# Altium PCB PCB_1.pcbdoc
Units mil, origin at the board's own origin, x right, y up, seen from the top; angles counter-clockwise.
Board outline 2237.91 x 3835.19 mil, 2 copper layers (Top Layer, Bottom Layer); 69 components, 62 nets, 255 pads, 151 vias.
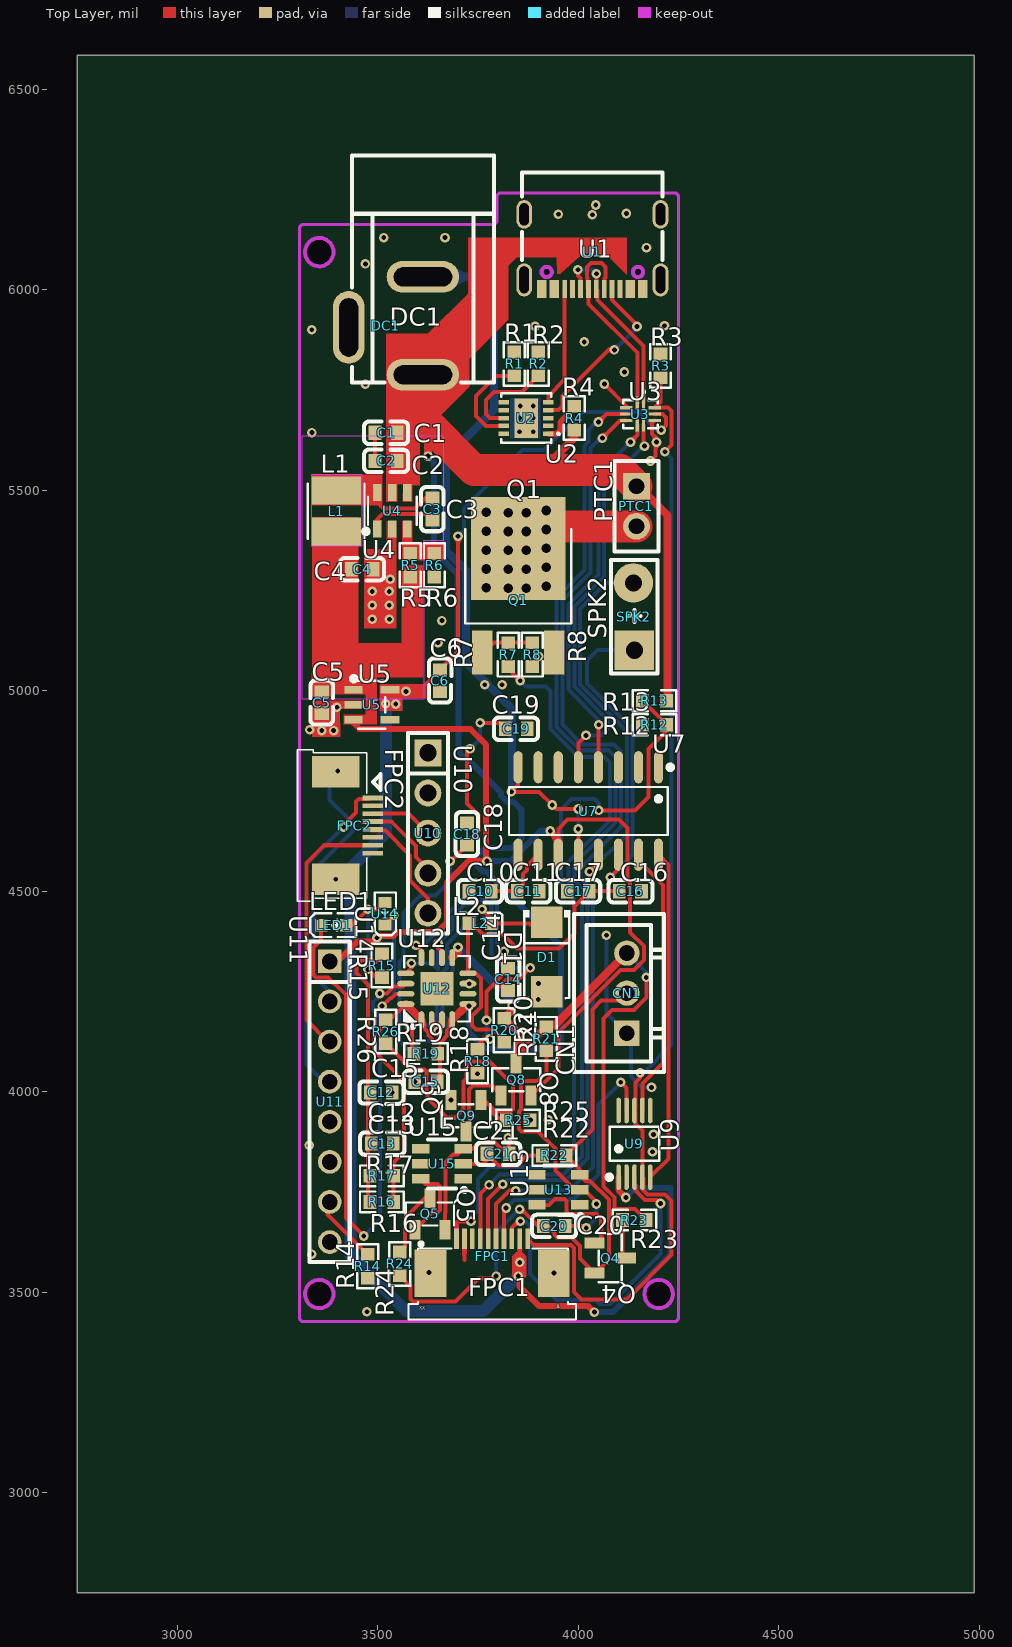
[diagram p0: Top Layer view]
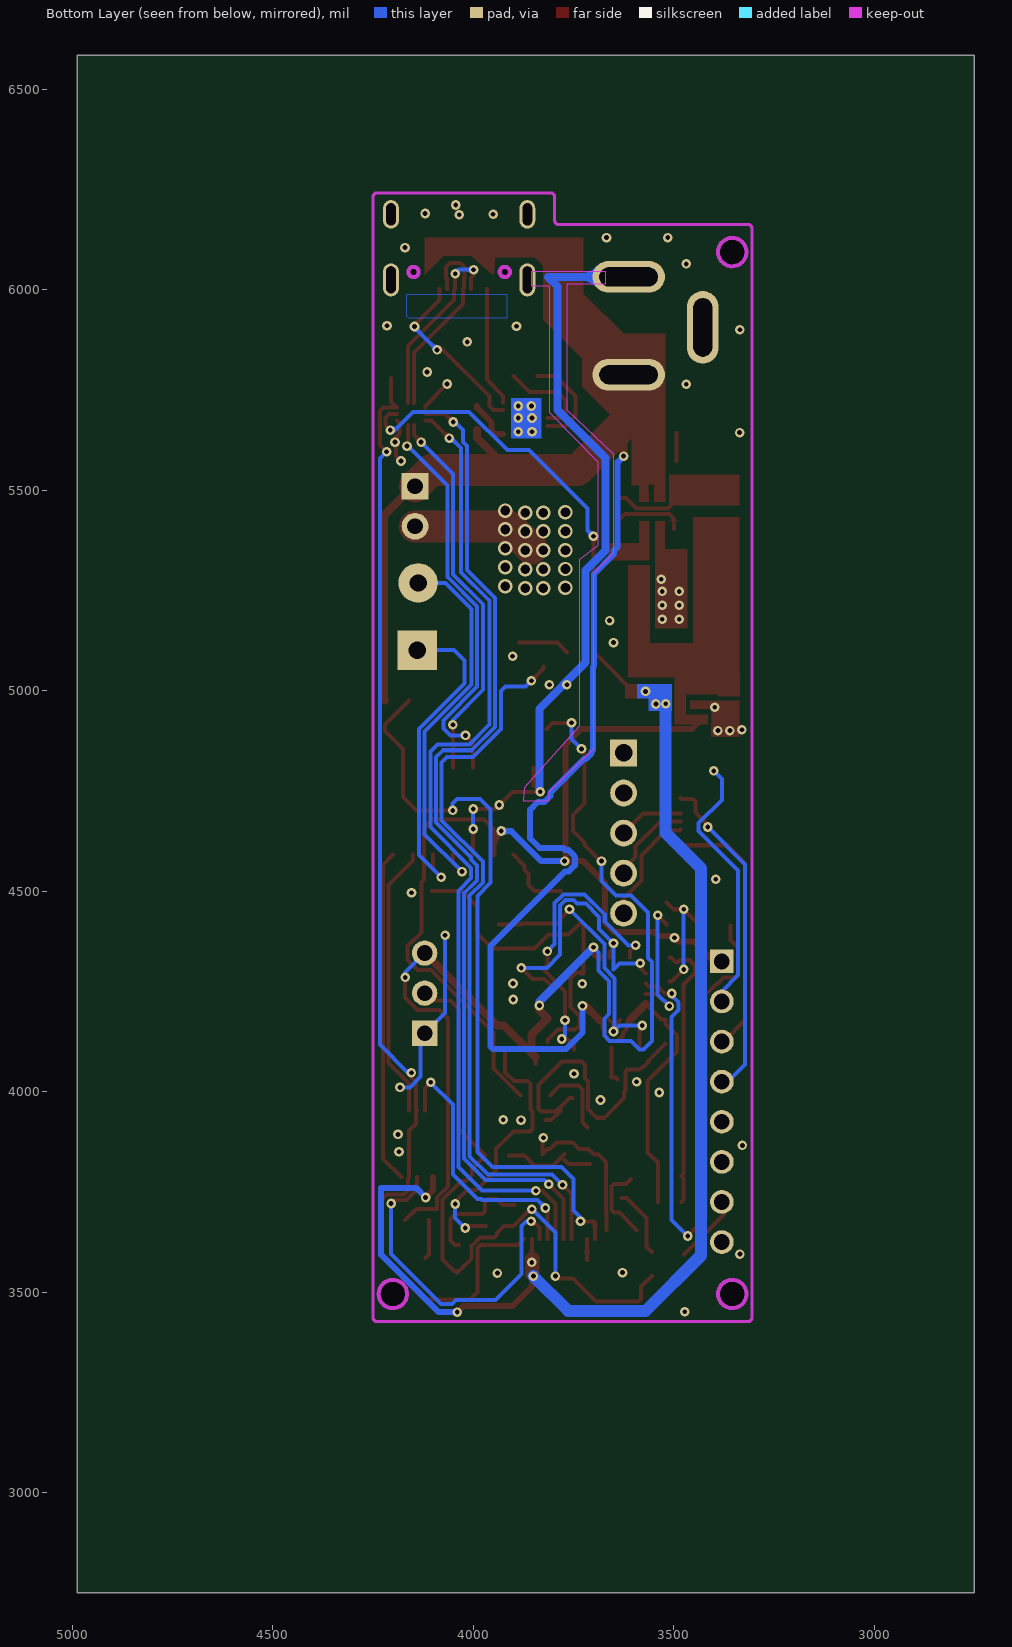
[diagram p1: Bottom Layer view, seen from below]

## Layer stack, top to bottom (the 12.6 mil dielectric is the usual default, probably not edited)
Top Layer: signal copper (thickness not stored)
Dielectric: dielectric 12.6, FR-4, Dk 4.8
Bottom Layer: signal copper (thickness not stored)

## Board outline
4987.91,2750 2750,2750 2750,6585.19 4987.91,6585.19
cut-out: 3389.43,6093.89 ccw(c3354,6093.67) 3318.57,6093.89 ccw(c3354,6094.11)
cut-out: 3389.43,3495.47 ccw(c3354,3495.25) 3318.57,3495.47 ccw(c3354,3495.69)
cut-out: 4235.89,3495.47 ccw(c4200.45,3495.47) 4165.02,3495.47 ccw(c4200.45,3495.47)

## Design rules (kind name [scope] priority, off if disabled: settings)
BoardOutlineClearance copperThickness1oz [All] p0: genericclearance=10 ignorepadtopadclearanceinfootprint=FALSE except(0: Arc-SplitContinuation Track-SplitContinuation SMDPad-SplitContinuation THPad-SplitContinuation Via-SplitContinuation Fill-SplitContinuation Poly-SplitContinuation Region-SplitContinuation Text-SplitContinuation; 6: Track-CutoutEdge SMDPad-CutoutEdge THPad-CutoutEdge Via-CutoutEdge Region-CutoutEdge; 11.8: Track-OutlineEdge SMDPad-OutlineEdge THPad-OutlineEdge Via-OutlineEdge Fill-OutlineEdge Region-OutlineEdge Poly-OutlineEdge Text-OutlineEdge Fill-CutoutEdge)
BoardOutlineClearance copperThickness2oz [All] p0: genericclearance=10 ignorepadtopadclearanceinfootprint=FALSE except(0: Arc-SplitContinuation Track-SplitContinuation SMDPad-SplitContinuation THPad-SplitContinuation Via-SplitContinuation Fill-SplitContinuation Poly-SplitContinuation Region-SplitContinuation Text-SplitContinuation; 6: Track-CutoutEdge SMDPad-CutoutEdge THPad-CutoutEdge Via-CutoutEdge Region-CutoutEdge; 11.8: Track-OutlineEdge SMDPad-OutlineEdge THPad-OutlineEdge Via-OutlineEdge Fill-OutlineEdge Region-OutlineEdge Poly-OutlineEdge Text-OutlineEdge Fill-CutoutEdge)
Clearance copperThickness1oz [(InNet('GND') OR InNet('3V3') OR InNet('ADC_VIN') OR InNet('$2N1457') OR InNet('$2N1458') OR InNet('VIN') OR InNet('5V') OR InNet('$2N1719') OR InNet('ESP_TX') OR InNet('ESP_RX') OR InNet('DN1') OR InNet('DP1') OR InNet('$2N173') OR InNet('$2N169') OR InNet('$2N860') OR InNet('$2N846') OR InNet('$2N1461') OR InNet('$2N861') OR InNet('DAC') OR InNet('SPK2') OR InNet('SPK1') OR InNet('SCK') OR InNet('DOUT') OR InNet('CC1') OR InNet('DN') OR InNet('DP') OR InNet('CC2') OR InNet('USBDM') OR InNet('USBDP') OR InNet('CH7800_RX') OR InNet('CH7800_TX') OR InNet('SW') OR InNet('PTC') OR InNet('$2N3080') OR InNet('GPIO17') OR InNet('GPIO16') OR InNet('GPIO15') OR InNet('SCL') OR InNet('SDA') OR InNet('AD0') OR InNet('XDA') OR InNet('XCL') OR InNet('INT') OR InNet('$2N24838') OR InNet('$2N25111') OR InNet('$2N25200') OR InNet('$2N25373') OR InNet('$2N25939') OR InNet('BAT+') OR InNet('$2N25975') OR InNet('$2N26224') OR InNet('$2N25852') OR InNet('$2N24540') OR InNet('$2N24753') OR InNet('$2N26433') OR InNet('$2N26509') OR InNet('$2N26582') OR InNet('$2N26578') OR InNet('$2N27775') OR InNet('$2N27867') OR InNet('$2N28041') OR InNet('$2N26613'))] p1: gap=7 ignorepadtopadclearanceinfootprint=FALSE except(4: Track-Track; 6: Track-SMDPad SMDPad-SMDPad Track-THPad SMDPad-THPad THPad-THPad Track-Via SMDPad-Via THPad-Via Via-Via SMDPad-Fill THPad-Fill Via-Fill Fill-Fill Track-Region SMDPad-Region THPad-Region Via-Region Region-Region Track-Poly SMDPad-Poly THPad-Poly Via-Poly Fill-Poly Region-Poly Poly-Poly Track-Text SMDPad-Text THPad-Text Via-Text Fill-Text Region-Text Poly-Text Text-Text; 6.9: Track-Hole SMDPad-Hole THPad-Hole Via-Hole Fill-Hole Region-Hole Poly-Hole Text-Hole Sheet-Hole; 11.8: Track-Fill Fill-Region Track-Sheet SMDPad-Sheet THPad-Sheet Via-Sheet Fill-Sheet Region-Sheet Poly-Sheet Text-Sheet)
Clearance copperThickness2oz [All] p1: gap=7 ignorepadtopadclearanceinfootprint=FALSE except(6: Track-SMDPad SMDPad-SMDPad Track-THPad SMDPad-THPad THPad-THPad Track-Via SMDPad-Via THPad-Via Via-Via SMDPad-Fill THPad-Fill Via-Fill Fill-Fill Track-Region SMDPad-Region THPad-Region Via-Region Region-Region Track-Poly SMDPad-Poly THPad-Poly Via-Poly Fill-Poly Region-Poly Poly-Poly Track-Text SMDPad-Text THPad-Text Via-Text Fill-Text Region-Text Poly-Text Text-Text; 6.9: Track-Hole SMDPad-Hole THPad-Hole Via-Hole Fill-Hole Region-Hole Poly-Hole Text-Hole Sheet-Hole; 8: Track-Track; 11.8: Track-Fill Fill-Region Track-Sheet SMDPad-Sheet THPad-Sheet Via-Sheet Fill-Sheet Region-Sheet Poly-Sheet Text-Sheet)
DiffPairsRouting differentialPair [All] p1: maxuncoupledlength=10 minlimit=6 maxlimit=6 mostfreqgap=6 toplayer_minwidth=5 toplayer_prefwidth=10 toplayer_maxwidth=100 bottomlayer_minwidth=5 bottomlayer_prefwidth=10 bottomlayer_maxwidth=100
PasteMaskExpansion pasteMaskExpansion [All] p1: expansion=0
PlaneConnect innerPlane [All] p1: planeconnectstyle=Relief reliefexpansion=20 reliefentries=4 reliefconductorwidth=10 reliefairgap=10
PolygonConnect copperRegion [All] p1: connectstyle=Relief reliefentries=4 reliefconductorwidth=10 polygonreliefangle="90 Angle" airgapwidth=10
RoutingVias viaSize [All] p1: viastyle="Through Hole" holewidth=12.0078 minholewidth=11.811 maxholewidth=248.0314 width=24.0158 minwidth=19.685 maxwidth=393.7008
SolderMaskExpansion solderMaskExpansion [All] p1: useseparateexpansions=TRUE expansion=2 expansionbottom=2
Width copperThickness1oz [All] p1: maxlimit=100 minlimit=5 preferedwidth=10
Width copperThickness2oz [All] p1: maxlimit=100 minlimit=8 preferedwidth=10

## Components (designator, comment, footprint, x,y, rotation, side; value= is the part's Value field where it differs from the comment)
C1 "CGA0603X7R104K500JT" C0603 3520.47,5643.23 r180 top
C2 "CL10A106KP8NNNC" C0603 3520.47,5573.23 r180 top
C3 "CGA0603X7R104K500JT" C0603 3636.08,5453.01 r90 top
C4 "CGA0603X7R104K500JT" C0603 3461.08,5303.01 r0 top
C5 "CGA0603X7R104K500JT" C0603 3360,4970 r270 top
C6 "CL10A106KP8NNNC" C0603 3655,5025 r270 top
C10 "CL10A105KA8NNNC" C0603 3755,4500 r0 top
C11 "CL10A105KA8NNNC" C0603 3875,4500 r180 top
C12 "CAP_0603" C0603 3508.46,3997.99 r180 top
C13 "CAP_0603" C0603 3510.77,3870.55 r180 top
C14 "CAP_0603" C0603 3825,4280 r90 top
C15 "CAP_0603" C0603 3620,4025 r180 top
C16 "CAP_0603" C0603 4130.12,4500 r180 top
C17 "CAP_0603" C0603 4000,4500 r0 top
C18 "CAP_0603" C0603 3722.44,4642.56 r90 top
C19 "CAP_0603" C0603 3845,4905 r0 top
C20 "CAP_0603" C0603 3940,3665 r0 top
C21 "CAP_0603" C0603 3800,3845 r180 top
CN1 "ZX-XH2.54-3PZZ" CONN-TH_3P-P2.54_2501S-3P 4120.95,4245.71 r90 top
D1 "SS34_C8678" SMA_L4.3-W2.6-LS5.2-RD 3921.25,4335.87 r270 top
DC1 "DC005" DC-IN-TH_DC005 3520,5910 r270 top locked
FPC1 "F0501-T-10-20T-R" FPC-SMD_F0501-T-10-20T-R 3785,3590 r0 top
FPC2 "F0501-T-08-20T-R" FPC-SMD_8P-P0.50_L4.4-W9.6 3441.34,4663.81 r270 top
L1 "CD32-4R7M 4.7UH" IND-SMD_L3.5-W3.0 3396.08,5448.01 r90 top
L2 "L_0603" l0603 3755,4420 r0 top
LED1 "XL-1608SURC-06" LED0603-RD_RED 3390,4415 r0 top
PTC1 "HDR-F_2.54_1x2P" HDR-TH_2P-P2.54-V-F 4145,5460 r270 top
Q1 "AOD4184L" TO-252-2_L6.6-W6.1-P4.57-LS9.9-TL-CW 3850,5225 r90 top
Q4 "SI2302_C2891732" SOT-23-3_L2.9-W1.3-P1.90-LS2.4-BR 4080,3585 r180 top
Q5 "SI2302_C2891732" SOT-23-3_L2.9-W1.3-P1.90-LS2.4-BR 3630,3695 r270 top
Q8 "IRLML6402_C518785" SOT-23-3_L2.9-W1.3-P1.90-LS2.4-BR 3845,4030 r270 top
Q9 "MMBT3904(RANGE:100-300)" SOT-23-3_L2.9-W1.3-P1.90-LS2.4-BR 3720,3940 r90 top
R1 "0603WAF1002T5E" R0603 3840,5815 r90 top
R2 "0603WAF1002T5E" R0603 3900,5815 r90 top
R3 "0603WAF1002T5E" R0603 4205,5810 r270 top
R4 "0603WAF100JT5E" R0603 3990,5680 r270 top
R5 "FRC0603F2703TS" R0603 3581.08,5313.01 r270 top
R6 "0603WAF5102T5E" R0603 3641.08,5313.01 r90 top
R7 "0603WAF1000T5E" R0603 3825,5090 r90 top
R8 "0603WAF1002T5E" R0603 3885,5090 r270 top
R12 "0603WAF5102T5E" R0603 4190,4915 r180 top
R13 "0603WAF2703T5E" R0603 4190,4975 r180 top
R14 "Res_0603" R0603 3474.66,3564.66 r90 top
R15 "Res_0603" R0603 3510.34,4314.66 r90 top
R16 "Res_0603" R0603 3510,3725 r180 top
R17 "Res_0603" R0603 3510,3790 r180 top
R18 "Res_0603" R0603 3748.73,4076.05 r270 top
R19 "Res_0603" R0603 3620,4095 r0 top
R20 "Res_0603" R0603 3814.89,4153.19 r270 top
R21 "Res_0603" R0603 3920.24,4131.73 r90 top
R22 "Res_0603" R0603 3940.24,3840.91 r0 top
R23 "Res_0603" R0603 4140,3680 r0 top
R24 "Res_0603" R0603 3554.66,3570.34 r270 top
R25 "Res_0603" R0603 3849.62,3929.04 r0 top
R26 "Res_0603" R0603 3520,4150 r270 top
SPK2 "GSPK3013P-8R0.15W" SPK-TH_BD30.0-P15.00-D0.8-L-RD 4140,5185 r90 top
U1 "TYPE-C16PIN" USB-C-SMD_TYPE-C16PIN 4035,6095 r180 top
U2 "HUSB238_002DD" DFN-10_L3.0-W3.0-P0.50-BL-EP2.5 3870,5680 r90 top
U3 "BL1532TQFN" QFN-10_L1.4-W1.8-P0.40-BL 4155,5690 r180 top
U4 "RY8411_C2935411" SOT-23-6_L2.9-W1.6-P0.95-LS2.8-TL 3536.14,5448.63 r90 top
U5 "ME6212C33M5G" SOT-23-5_L3.0-W1.7-P0.95-LS2.8-BL 3485,4965 r270 top
U7 "CH7800" SOP-16_L9.9-W3.9-P1.27-LS6.0-BL 4025,4700 r180 top
U9 "BL1555MM" MSOP-10_L3.0-W3.0-P0.50-LS5.0-BL 4140,3870 r0 top
U10 "HB-PH3-25415PB2GOP" HDR-TH_5P-P2.54-V-M 3625,4645 r270 top
U11 "HB-PH3-25418PB2GOP" HDR-TH_8P-P2.54-V-M 3380,3975 r270 top
U12 "TP5100" TQFN-16_L4.0-W4.0-P0.65-BL-EP 3647.21,4256.78 r0 top
U13 "HY2213-BB3A" SOT-23-6_L2.9-W1.6-P0.95-LS2.8-BR 3950,3755 r0 top
U14 "42-51/GHC-YW2X2K/3T" LED-SMD_L1.6-W0.8-FD_GREEN-1 3517.8,4443.7 r270 top
U15 "HY2213-BB3A" SOT-23-6_L2.9-W1.6-P0.95-LS2.8-BR 3660,3820 r0 top

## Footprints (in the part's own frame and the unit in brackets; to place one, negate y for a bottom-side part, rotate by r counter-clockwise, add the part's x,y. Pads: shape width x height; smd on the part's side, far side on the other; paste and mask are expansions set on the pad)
C0603 [mm]
  rect 0.8x0.9 smd: 1(-0.7,0) 2(0.7,0)
  silkscreen extent -1.41,-0.71 1.39,0.72
CONN-TH_3P-P2.54_2501S-3P [mm]
  rect 1.6x1.6 hole 1: 1(-2.54,0)
  round 1.6 hole 1: 2(0,0) 3(2.54,0)
  silkscreen extent -4.98,-2.35 5.02,3.35
DC-IN-TH_DC005 [mm]
  oval 2x4.6 hole 1.2 slot 3.7 at 90 deg: 1(3.1,2.35) 2(-3.1,2.35)
  oval 4.6x2 hole 1.2 slot 3.7 at 0 deg: 3(0.1,-2.35)
  silkscreen extent -10.8,-2.15 3.6,6.85
DFN-10_L3.0-W3.0-P0.50-BL-EP2.5 [mm]
  rect 0.28x0.665 smd: 1(-1,-1.407) 2(-0.5,-1.407) 3(0,-1.407) 4(0.5,-1.407) 5(1,-1.407) 6(1,1.407) 7(0.5,1.407) 8(0,1.407) 9(-0.5,1.407) 10(-1,1.407)
  rect 2.5x1.5 smd: 11(0,0)
  silkscreen extent -1.58,-2.12 1.58,1.58
FPC-SMD_8P-P0.50_L4.4-W9.6 [mm]
  rect 2x3 smd: 0(-3.4,-1.175) 0(3.4,-1.175)
  rect 0.3x1.3 smd: 1(-1.75,1.175) 2(-1.25,1.175) 3(-0.75,1.175) 4(-0.25,1.175) 5(0.25,1.175) 6(0.75,1.175) 7(1.25,1.175) 8(1.75,1.175)
  silkscreen extent -4.8,-3.6 4.8,1.68
FPC-SMD_F0501-T-10-20T-R [mm]
  rect 0.3x1.3 smd: 1(-2.25,1.097) 2(-1.75,1.097) 3(-1.25,1.097) 4(-0.75,1.097) 5(-0.25,1.097) 6(0.25,1.097) 7(0.75,1.097) 8(1.25,1.097) 9(1.75,1.097) 10(2.25,1.097)
  rect 2x3 smd: 11(3.9,-1.097) 12(-3.9,-1.097)
  silkscreen extent -5.3,-4.03 5.3,0.87
HDR-TH_2P-P2.54-V-F [mm]
  rect 1.7x1.7 hole 1: 1(-1.27,0)
  round 1.7 hole 1: 2(1.27,0)
  silkscreen extent -2.88,-1.39 2.88,1.4
HDR-TH_5P-P2.54-V-M [mm]
  rect 1.7x1.7 hole 1.1: 1(-5.08,0)
  round 1.7 hole 1.1: 2(-2.54,0) 3(0,0) 4(2.54,0) 5(5.08,0)
  silkscreen extent -6.35,-1.27 6.35,1.27
HDR-TH_8P-P2.54-V-M [mm]
  rect 1.5x1.5 hole 1: 1(-8.89,0)
  round 1.5 hole 1: 2(-6.35,0) 3(-3.81,0) 4(-1.27,0) 5(1.27,0) 6(3.81,0) 7(6.35,0) 8(8.89,0)
  silkscreen extent -10.16,-1.27 10.16,1.27
IND-SMD_L3.5-W3.0 [mm]
  rect 1.8x3.12 smd: 1(1.303,0) 2(-1.303,0)
  silkscreen extent -1.75,-1.8 1.75,1.8
l0603 [mm]
  rect 0.8x0.864 smd: 1(-0.7,0) 2(0.7,0)
  silkscreen extent -1.42,-0.65 1.41,0.67
LED0603-RD_RED [mm]
  rect 0.8x0.8 smd: 1(-0.8,-0.003) 2(0.8,0.003)
  silkscreen extent -1.49,-0.75 1.39,0.76
LED-SMD_L1.6-W0.8-FD_GREEN-1 [mm]
  rect 0.7x0.8 smd: 1(-0.715,0) 2(0.715,0)
  silkscreen extent -1.35,-0.65 1.35,0.7
MSOP-10_L3.0-W3.0-P0.50-LS5.0-BL [mm]
  oval 0.28x1.62 smd: 1(-1,-2.11) 2(-0.5,-2.11) 3(0,-2.11) 4(0.5,-2.11) 5(1,-2.11) 6(1,2.11) 7(0.5,2.11) 8(0,2.11) 9(-0.5,2.11) 10(-1,2.11)
  silkscreen extent -1.74,-2.26 1.58,1.07
QFN-10_L1.4-W1.8-P0.40-BL [mm]
  rect 0.2x0.9 smd: 1(-0.2,-0.65)
  rect 0.2x0.8 smd: 2(0.2,-0.7) 6(0.2,0.7) 7(-0.2,0.7)
  rect 0.8x0.2 smd: 3(0.9,-0.4) 4(0.9,0) 5(0.9,0.4) 8(-0.9,0.4) 9(-0.9,0) 10(-0.9,-0.4)
  silkscreen extent -1.1,-1.48 1.09,0.91
R0603 [mil]
  rect 31.75x34.02 smd: 1(-29.66,0) 2(29.66,0)
  silkscreen extent -55,-26 55,26
SMA_L4.3-W2.6-LS5.2-RD [mm]
  rect 2x2 smd: 1(-2.2,0) 2(2.2,0)
  silkscreen extent -2.98,-1.5 2.6,1.5
SOP-16_L9.9-W3.9-P1.27-LS6.0-BL [mil]
  oval 22.6x80.24 smd: 1(-175,-109.02) 2(-125,-109.02) 3(-75,-109.02) 4(-25,-109.02) 5(25,-109.02) 6(75,-109.02) 7(125,-109.02) 8(175,-109.02) 9(175,109.02) 10(125,109.02) 11(75,109.02) 12(25,109.02) 13(-25,109.02) 14(-75,109.02) 15(-125,109.02) 16(-175,109.02)
  silkscreen extent -210,-115 198,60
SOT-23-3_L2.9-W1.3-P1.90-LS2.4-BR [mm]
  rect 1.25x0.7 smd: 1(1,-0.95) 2(1,0.95) 3(-1,0)
  silkscreen extent -0.73,-1.53 0.73,1.53
SOT-23-5_L3.0-W1.7-P0.95-LS2.8-BL [mm]
  rect 0.49x1.157 smd: 1(-0.95,-1.154) 2(0,-1.154) 3(0.95,-1.154)
  rect 0.49x1.175 smd: 4(0.95,1.154) 5(-0.95,1.154)
  silkscreen extent -1.8,-1.29 1.53,0.85
SOT-23-6_L2.9-W1.6-P0.95-LS2.8-BR [mm]
  rect 1.1x0.6 smd: 1(1.35,-0.95) 2(1.35,0) 3(1.35,0.95) 4(-1.35,0.95) 5(-1.35,0) 6(-1.35,-0.95)
  silkscreen extent -0.9,-1.78 1.52,1.55
SOT-23-6_L2.9-W1.6-P0.95-LS2.8-TL [mil]
  rect 42.2x20.95 smd: 1(-45.24,37.4) 2(-45.24,0) 3(-45.24,-37.4) 4(45.24,-37.4) 5(45.24,0) 6(45.24,37.4)
  silkscreen extent -57,-61 35,72
SPK-TH_BD30.0-P15.00-D0.8-L-RD [mm]
  rect 2.5x2.5 hole 1.1: 1(-2.128,0)
  round 2.5 hole 1.1: 2(2.128,0.064)
  silkscreen extent -3.59,-1.47 3.57,1.5
TO-252-2_L6.6-W6.1-P4.57-LS9.9-TL-CW [mm]
  rect 2.8x1.3 smd: 1(-3.292,2.273) 3(-3.292,-2.273)
  rect 6.5x6 smd: 2(3.292,0)
  silkscreen extent -1.46,-3.35 4.51,3.34
TQFN-16_L4.0-W4.0-P0.65-BL-EP [mil]
  oval 14.33x42.8 smd: 1(-38.39,-77.5) 2(-12.79,-77.5) 3(12.8,-77.5) 4(38.39,-77.5) 9(38.39,77.5) 10(12.8,77.5) 11(-12.79,77.5) 12(-38.39,77.5)
  oval 42.8x14.33 smd: 5(77.5,-38.39) 6(77.5,-12.8) 7(77.5,12.79) 8(77.5,38.39) 13(-77.5,38.39) 14(-77.5,12.79) 15(-77.5,-12.8) 16(-77.5,-38.39)
  rect 82.68x82.68 smd: 17(0,0)
  silkscreen extent -82,-99 82,82
USB-C-SMD_TYPE-C16PIN [mm]
  oval 1x2.1 hole 0.6 slot 1.7 at 90 deg: 1(-4.32,1.787) 2(4.32,1.787)
  oval 1x1.8 hole 0.6 slot 1.4 at 90 deg: 3(-4.32,-2.362) 4(4.32,-2.362)
  rect 0.6x1.15 smd: A1B12(-3.2,2.362) A4B9(-2.4,2.362) B1A12(3.2,2.362) B4A9(2.4,2.362)
  rect 0.3x1.15 smd: A5(-1.25,2.362) A6(-0.25,2.362) A7(0.25,2.362) A8(1.25,2.362) B5(1.75,2.362) B6(0.75,2.362) B7(-0.75,2.362) B8(-1.75,2.362)
  Board Outline Layer circle w0.005: c2.89,1.288 r0.325
  Board Outline Layer circle w0.005: c-2.89,1.288 r0.325
  Board Outline Layer circle w0.254: c2.89,1.288 r0.325
  Board Outline Layer circle w0.254: c-2.89,1.288 r0.325
  Multi-Layer board cut-out: 2.565,1.288 2.611,1.128 2.729,1.012 2.89,0.969 3.051,1.012 3.169,1.128 3.215,1.288 3.215,1.288 3.169,1.448 3.051,1.564 2.89,1.607 2.729,1.564 2.611,1.448 2.565,1.288
  Multi-Layer board cut-out: -3.215,1.288 -3.183,1.147 -3.093,1.034 -2.962,0.971 -2.818,0.971 -2.687,1.034 -2.597,1.147 -2.565,1.288 -2.565,1.288 -2.597,1.429 -2.687,1.542 -2.818,1.605 -2.962,1.605 -3.093,1.542 -3.183,1.429 -3.215,1.288
  silkscreen extent -4.45,-5 4.45,0.52

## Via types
v1: diameter 24.02, hole 12.01, Top Layer to Bottom Layer, 131 vias
v2: diameter 36, hole 24, Top Layer to Bottom Layer, 20 vias

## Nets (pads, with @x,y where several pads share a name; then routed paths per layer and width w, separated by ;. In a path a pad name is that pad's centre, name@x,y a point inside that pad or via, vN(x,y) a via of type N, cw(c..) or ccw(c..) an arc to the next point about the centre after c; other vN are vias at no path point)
3V3: C6.1 FPC1.9 U3.9 U5.5 U9.1 | length 4064.2
  Top Layer w10: v1(3570.37,4998.32) 3600.76,4998.32 3618.64,5016.2 3620.45,5016.2 3630.3,5026.05 3630.3,5027.86 C6.1 3700,5097.56 v1(3700,5385) ; v1(3853.89,3574.35) FPC1.9 ; U3.9 4209.91,5690 4218.84,5681.07 4218.84,5661.83 v1(4207.01,5650)
  Top Layer w15: v1(3853.89,3574.35) 3853.89,3513.98 3902.48,3465.39 4025,3465.39 v1(4040,3450.39) ; U9.1 4100.63,3754.37 4101.32,3753.68 4101.32,3752.68 4112.45,3741.56 4113.44,3741.56 v1(4118.76,3736.24)
  Bottom Layer w10: v1(3700,5385) 3715,5400 3715,5454.4 3860.6,5600 3915,5600 4010,5695 4150,5695 4195,5650 v1(4207.01,5650)
  Bottom Layer w15: v1(4040,3450.39) 4086.24,3450.44 4230.36,3594.55 4230.36,3760 4142.52,3760 v1(4118.76,3736.24)
  Bottom Layer w30: v1(3520,4967.56) 3520,4645 3432.01,4557.01 3432.01,3591.38 3570,3453.39 3763.39,3453.39 v1(3850,3540)
  other v1: 3544.55,4966.86
5V: C4.1 C5.1 L1.2 Q8.2 R5.2 U5.1 U5.3 U7.11 U11.1 | length 2474.7
  Top Layer w10: Q8.2 3950,4058.23 3950,4147.86 4105.37,4303.23 4138.56,4303.23 4163.44,4328.11 4163.44,4363.31 4129.29,4397.45 4129.29,4522.27 4122.28,4529.28 4122.28,4657.72 4101.4,4678.6 3973.6,4678.6 3950,4655 U7.11@3950,4630
  Top Layer w15: U11.1@3400,4325 3450,4375 3489.22,4375 v1(3497.99,4383.77) 3502.5,4388.28 3539.13,4388.28 3548.9,4398.05 3648.05,4398.05 3671.95,4421.95 3671.95,4521.1 3725.85,4575 3770,4575 3770,4865 3730.53,4904.47 3454.58,4904.47 3439.58,4919.47 U5.3 ; v1(3930,4650) 3950,4630 U7.11
  Bottom Layer w15: v1(3772.14,4575) 3830,4575 3905,4650 v1(3930,4650)
$2N169: Q1.1 R7.2 R8.1 | length 129.5
  Top Layer w10: Q1.1@3765.52,5095.4 3789.78,5119.66 R7.2 R8.1
$2N173: PTC1.2 Q1.2 | length 312.9
  Top Layer w80: Q1.2@3855,5354.6 3910.39,5410 PTC1.2
  other v2: 3770,5256.42 3825,5255.71 3870,5255.71 3920,5260.71 3825,5302.85 3870,5302.85 3770,5303.56 3920,5307.85 3825,5350 3870,5350 3770,5350.71 3920,5355 3825,5397.15 3870,5397.15 3770,5397.85 3920,5402.15 3825,5444.29 3870,5444.29 3770,5445 3920,5449.29
$2N846: R4.1 U2.1 | length 107.6
  Top Layer w15: U2.1 3945.63,5640.63 3955,5650 3955,5670.22 3990,5705.22 R4.1
$2N860: R1.1 U2.9 | length 245.7
  Top Layer w10: U2.9 3769.68,5660.32 3745,5685 3745,5735 3795.34,5785.34 R1.1
$2N861: R2.1 U2.8 | length 238.7
  Top Layer w10: U2.8 3780,5680 3770,5690 3770,5725 3790,5745 3859.66,5745 R2.1
$2N1457: C3.2 L1.1 U4.6 | length 178.9
  Top Layer w10: U4.6 3504.36,5488.26 3504.36,5464.02 3514.2,5454.17 3592.39,5454.17 3618.79,5480.57 C3.2
$2N1458: C3.1 U4.1 | length 173
  Top Layer w10: U4.1 3498.74,5427.82 3511.08,5440.15 3621.38,5440.15 C3.1
$2N1461: R5.1 R6.2 U4.3
$2N1719: C10.2 C11.2 U7.10 | length 177.6
  Top Layer w10: C10.2 C11.2 3862.44,4515 3862.44,4543.09 3872.28,4552.93 3872.28,4563.26 U7.10
$2N3080: FPC1.3
$2N24540: LED1.1 U12.14 | length 1564.2
  Top Layer w10: LED1.1 3358.52,4378.11 3339.49,4359.08 3339.49,4290.92 3345.92,4284.49 3375.51,4284.49 3390,4270 3392.29,4270 3420.51,4241.78 3420.51,3684.49 v1(3465,3640) ; v1(3505,4245) 3522.39,4245 3539.52,4262.13 3562.27,4262.13 U12.14
  Bottom Layer w10: v1(3465,3640) 3505,3680 3505,4186.76 3487.75,4204 3487.75,4223.05 3505,4240.3 v1(3505,4245)
$2N24753: LED1.2 R15.1 U14.1 | length 317.6
  Top Layer w10: LED1.2 3435.14,4415.14 v1(3475,4455) 3500.95,4455 U14.1 ; v1(3475,4305) 3505,4275 R15.1@3510.34,4275
  Bottom Layer w10: v1(3475,4305) v1(3475,4455)
$2N24838: C12.2 C13.2 R15.2 R16.2 R17.2 | length 683.2
  Top Layer w10: R16.2 3475.33,3730.01 3475.33,3784.99 R17.2 3475,3795.34 3475,4267.48 3447.01,4295.48 3447.01,4314.52 3460.48,4327.99 3484.52,4327.99 3489.52,4322.99 3495.34,4322.99 3506.67,4334.32 R15.2@3510.34,4334.32
$2N25111: C14.2 R18.1 U12.12 | length 733.5
  Top Layer w10: v1(3595,4365) 3608.82,4351.18 U12.12 ; R18.1 3748.73,4115.71 3764.55,4131.53 v1(3779.38,4131.53) ; v1(3770.98,4177.99) 3770.98,4204.94 3771.11,4205.06 3771.11,4249.49 3803.74,4282.13 3803.74,4283.74 3825,4305 C14.2 3815,4317.56 v1(3815,4350)
  Bottom Layer w10: v1(3595,4365) 3612.48,4365 3671.97,4424.48 3671.97,4441.61 3722.37,4492.01 3775.33,4492.01 3797.01,4470.33 3797.01,4367.99 v1(3815,4350) ; v1(3770.98,4177.99) 3770.98,4139.92 v1(3779.38,4131.53)
$2N25200: C14.1 U12.10 U12.13 | length 749.2
  Top Layer w10: U12.13 3583.66,4309.12 v1(3583.66,4320.17) ; v1(3650,4370) 3650,4358.6 3660,4348.6 U12.10 ; 3800,4252.44 3800,4258.56 3822.27,4280.83 3852.01,4280.83 v1(3880,4308.82)
  Bottom Layer w10: v1(3583.66,4320.17) 3634.83,4320.17 3650,4305 v1(3650,4370) 3685.98,4405.98 3685.98,4435.81 3719.19,4469.02 3741.5,4469.02 3750.48,4477.99 3769.52,4477.99 3782.99,4464.52 3782.99,4342.01 3816.18,4308.82 v1(3880,4308.82)
$2N25373: C15.1 R19.2 | length 91.1
  Top Layer w10: C15.1@3640,4030.73 3644.27,4035 3654.66,4035 R19.2@3654.66,4109.66
$2N25852: D1.1 L2.2 R19.1 U12.2 U12.3 | length 739.1
  Top Layer w10: v1(3578.66,4165.23) 3585.34,4158.55 R19.1@3585.34,4110 ; U12.2 3650.01,4163.69 ; v1(3650.01,4150) 3650.01,4163.69 ; U12.3 3650.01,4169.28 3650.01,4163.69 ; v1(3760,4455) 3782.55,4432.44 L2.2 3878.74,4420 3881.25,4417.48 D1.1@3936.25,4417.48
  Bottom Layer w10: v1(3578.66,4165.23) 3634.78,4165.23 v1@3647.21,4152.8 ; v1(3650.01,4150) v1@3647.21,4152.8 ; v1(3760,4455) 3672.99,4367.99 3672.99,4308.17 3647.21,4282.39 v1@3647.21,4152.8
$2N25939: C16.2 C17.2 L2.1 R20.2 U12.8 | length 891.2
  Top Layer w10: R20.2 3814.89,4128.52 3788.42,4155 3745,4155 3735,4165 3735,4188.78 3757.09,4210.87 3757.09,4282.08 3742.37,4296.81 3731.36,4296.81 3729.71,4295.17 U12.8 3724.71,4417.27 L2.1 3734.26,4420 3762.26,4392.01 3812.45,4392.01 3847.33,4357.13 3952.13,4357.13 3990,4395 3990,4462.44 C17.2 C16.2
$2N25975: C20.2 R21.1 U13.2 | length 672.5
  Top Layer w10: R21.1 3920.24,4048.29 3898.17,4026.22 3864.07,4026.22 3857.64,4019.79 3857.64,3955.82 3852.42,3950.6 3852.42,3907.48 3858.85,3901.05 3899.7,3901.05 3943.04,3857.72 3943.04,3803.52 3991.55,3755 U13.2 4015,3755 4045.13,3724.87 4045.13,3720.13 v1(4045,3720) ; C20.2 4015,3665 v1(4020,3660)
  Bottom Layer w10: v1(4020,3660) 4045,3685 v1(4045,3720)
$2N26224: C21.2 R22.1 U15.2 | length 228.6
  Top Layer w10: U15.2@3708.15,3820 3762.44,3820 C21.2@3772.44,3830 ; C21.2 3801.14,3816.3 3847.86,3816.3 3872.47,3840.91 R22.1
$2N26433: Q4.1 U13.6 | length 282.5
  Top Layer w10: U13.6 3926.85,3717.6 3941.45,3732.2 3965.83,3732.2 3970.51,3727.52 3970.51,3701.24 3976.95,3694.8 4045.2,3694.8 4057.21,3682.79 4057.21,3628.98 4045.63,3617.4 Q4.1@4035.63,3617.4
$2N26509: Q4.3 R23.1 | length 98.7
  Top Layer w10: R23.1 4110.34,3594.03 Q4.3
$2N26578: Q5.3 R24.1 | length 172.9
  Top Layer w10: R24.1 3567.84,3613.18 3567.84,3684.79 3617.42,3734.37 Q5.3
$2N26582: Q5.1 U15.6 | length 196.8
  Top Layer w10: Q5.1 3635.75,3698.78 3648.33,3698.78 3654.76,3705.21 3654.76,3763.53 3648.33,3769.96 3619.49,3769.96 U15.6
$2N26613: U12.15 U14.2 | length 343.8
  Top Layer w10: v1(3510.74,4213.53) 3531.18,4233.97 3534.72,4233.97 3544.73,4243.98 U12.15 ; U14.2 3517.8,4417.8 v1(3540,4440)
  Bottom Layer w10: v1(3510.74,4213.53) 3540,4242.78 v1(3540,4440)
$2N27775: Q8.1 Q9.3 | length 194.3
  Top Layer w10: Q9.3@3715,3910.63 3727.64,3923.27 3727.64,4004.96 3737.64,4014.96 3784.18,4014.96 3807.6,3991.54 Q8.1
$2N27867: Q9.1 R25.1 R26.2 | length 793.5
  Top Layer w10: R26.2 3563.48,4076.86 3563.48,4073.44 3574.91,4062.01 3578.33,4062.01 3585.19,4055.15 3616.08,4055.15 3620.83,4050.41 3620.83,4002.73 3624.17,3999.39 3624.17,3983.88 3673.05,3935 3692.15,3935 3713.62,3956.47 3713.62,4025.33 3720.74,4032.45 3720.74,4066.81 3727.17,4073.25 3728.61,4073.25 3730.36,4075 3778.53,4075 3837.36,4016.17 3837.36,3956.47 3830.93,3950.04 3794.27,3950.04 3782.84,3961.47 ; Q9.1@3752.4,3984.37 3759.94,3984.37 3782.84,3961.47 ; R25.1 3805.96,3929.04 3782.84,3952.16 3782.84,3961.47
$2N28041: C20.1 CN1.2 Q4.2 R22.2 R24.2 U13.3 | length 1633.3
  Top Layer w10: R24.2 3581.1,3514.24 3581.1,3483.22 3587.54,3476.78 3693.21,3476.78 3750.76,3534.33 3789.33,3534.33 v1(3795,3540) ; v1(3853.7,3706.95) 3860.94,3699.71 3865.19,3699.71 3899.89,3665 C20.1 3923.23,3665 3940.83,3647.4 3940.83,3642.73 3947.26,3636.3 3982.85,3636.3 4003.68,3615.47 4003.68,3584.55 Q4.2@4035.63,3552.6 ; Q4.2 Q4.2@4035.63,3552.6 ; CN1.2 4102.32,4227.07 4057.07,4227.07 4035,4205 4035,3906.02 R22.2 4003.15,3807.66 U13.3 4017.75,3777.8 4029.35,3777.8 4076.22,3730.93 4076.22,3581.22 4047.6,3552.6 Q4.2@4035.63,3552.6
  Bottom Layer w10: v1(3795,3540) 3795,3648.65 3846.1,3699.75 3846.51,3699.75 v1(3853.7,3706.95)
AD0: R14.2 U11.7 | length 172
  Top Layer w10: U11.7@3375,3725 3375,3693.98 R14.2
ADC_VIN: FPC1.1 R12.1 R13.2 | length 1874.3
  Top Layer w10: FPC1.1 3696.41,3673.59 3699.59,3676.76 v1(3732.48,3676.76) ; v1(4051.18,4701.59) 4141.59,4701.59 4175,4735 4175,4855 4219.66,4899.66 R12.1 4219.66,4915.68 R13.2
  Bottom Layer w10: v1(3732.48,3676.76) 3732.48,3686.76 3749.49,3703.77 3749.49,3782.04 3779.74,3812.28 3952.28,3812.28 3989.75,3849.75 3989.75,4488.27 3956.75,4521.27 3956.75,4704.23 3982.52,4730 4040,4730 4051.18,4718.82 v1(4051.18,4701.59)
BAT+: C18.1 C19.1 CN1.3 Q8.3 R20.1 R21.2 R23.2 U12.9 | length 2972.4
  Top Layer w10: v1(3680,4575) 3682.44,4575 C18.1 3722.44,4621.12 3751.14,4649.82 3751.14,4690.42 3722.44,4719.12 3722.44,4847.44 v1(3730,4855) ; v1(3755,4920) 3802.44,4920 C19.1 ; Q8.3 Q8.3@3845,4086.16 ; R23.2 4141.67,3707.99 4090.24,3707.99 4090.24,3736.73 4062.88,3764.09 4062.88,4182.39 4083.71,4203.23 4138.56,4203.23 4169.66,4234.33 v1(4169.66,4285)
  Top Layer w20: U12.9 v1@3700,4348.68 ; v1(3835,4215) 3835,4202.95 R20.1 3855,4142.74 3855,4096.16 ; Q8.3@3845,4086.16 3855,4096.16 ; R21.2 3855,4096.16 ; R21.2@3923.84,4165 3940.25,4165 CN1.3
  Bottom Layer w10: v1(3680,4575) 3680,4526.04 3643.41,4489.45 3606.59,4489.45 3564.02,4446.88 3564.02,4333.04 3554.02,4323.04 3554.02,4125.98 3575,4105 3585,4105 3607.01,4127.01 3659.53,4127.01 3673,4140.48 3673,4181.92 3661.21,4193.71 3661.21,4276.57 3687.01,4302.37 3687.01,4347.01 v1(3700,4360) ; v1(3730,4855) 3755,4880 v1(3755,4920) ; CN1.3 4169.66,4297.01 v1(4169.66,4285)
  Bottom Layer w20: v1(3700,4360) 3835,4225 v1(3835,4215)
CC1: U1.A5 U2.4 | length 442.7
  Top Layer w10: U2.4 3950,5699.69 3960,5709.69 3960,5735 4075,5850 v1(4090,5850) ; U1.A5@4084.21,6001.88 4084.21,5974.56 4146.38,5912.39 v1(4146.38,5908.47)
  Bottom Layer w10: v1(4090,5850) 4146.38,5906.38 v1(4146.38,5908.47)
CC2: U1.B5 U2.5 | length 299.4
  Top Layer w10: U2.5 3925.41,5735.41 3966.1,5776.1 U1.B5@3966.1,6001.88
CH7800_RX: U7.16 U9.5 | length 833.3
  Top Layer w10: U9.5 4225,3832.56 4225,4565.98 U7.16
CH7800_TX: U7.15 U9.7 | length 684.4
  Top Layer w10: U7.15 4150,4576.84 4210.98,4515.85 4210.98,4071.47 4159.69,4020.18 U9.7
DAC: U7.9
DN: U1.A7 U1.B7 U3.2 | length 502.2
  Top Layer w10: U1.B7@4064.53,6001.88 4065,6002.35 4065,6027.48 4067.99,6030.48 4067.99,6057.01 4057.93,6067.07 4032.07,6067.07 4022.01,6057.01 4022.01,6030.48 4022.93,6029.56 4022.93,6004.11 4025.16,6001.88 4025.16,5964.84 4147.13,5842.87 U3.2
DN1: FPC1.5 U3.4 | length 2507.7
  Top Layer w10: FPC1.5 3775.16,3732.67 v1(3811.74,3769.25) ; v1(4050,5670) 4070,5690 U3.4
  Bottom Layer w10: v1(3811.74,3769.25) 3821.74,3779.25 3969.07,3779.25 4022.77,3832.94 4022.75,4494.91 3991.02,4526.65 3991.02,4564.09 4006.02,4579.09 4006.02,4584.09 4092.95,4671.03 4092.95,4834.1 4075.53,4851.52 4003.94,4851.52 3945.98,4909.48 3945.98,5230.81 4015.98,5300.81 4015.98,5610.81 4025,5619.82 4025,5650 4045,5670 v1(4050,5670)
DOUT: U9.10
DP: U1.A6 U1.B6 U3.1 | length 472.3
  Top Layer w10: v1(3999.02,6050) 3999.02,6035.98 4005.47,6029.53 U1.B6@4005.47,6001.88 ; v1(4045,6040) 4045,6002.04 4044.84,6001.88 4047.64,5999.08 4047.64,5974.69 4162.87,5859.46 U3.1@4162.87,5717.56
  Bottom Layer w10: v1(3999.02,6050) 4035,6050 v1(4045,6040)
DP1: FPC1.6 U3.5 | length 2470.1
  Top Layer w10: FPC1.6 3794.84,3719.84 3827.99,3752.99 v1(3843.8,3752.99) ; v1(4060,5630) 4104.25,5674.25 U3.5
  Bottom Layer w10: v1(3843.8,3752.99) 3977.99,3752.99 4036.77,3811.77 4036.77,4500.72 4005.03,4532.45 4005.03,4558.28 4106.97,4660.22 4106.97,4848.03 4089.46,4865.54 4009.74,4865.54 3960,4915.28 3960,5225 4030,5295 4030,5605 4055,5630 v1(4060,5630)
ESP_RX: FPC1.7 U9.9 | length 673.8
  Top Layer w10: FPC1.7 3814.53,3704.53 v1(3820,3710) ; v1(4106.01,4023.5) 4120.32,4009.19 U9.9
  Bottom Layer w10: v1(3820,3710) 3840,3730 3977.48,3730 3979.49,3732.01 3989.52,3732.01 4050.77,3793.25 4050.77,3968.25 v1(4106.01,4023.5)
ESP_TX: FPC1.8 U9.3 | length 848.4
  Top Layer w10: FPC1.8 3835,3633.96 3835,3661.31 3843.44,3669.75 3848.62,3669.75 v1(3855.63,3676.76) ; U9.3 4140,3770.2 4143.19,3767.01 4143.19,3753.58 4166.73,3730.04 4195.89,3730.04 v1(4204.87,3721.06)
  Bottom Layer w10: v1(3855.63,3676.76) 3868.24,3676.76 3880,3665 3880,3545 3945,3480 4042.91,3480 4052.91,3470 4080,3470 4204.87,3594.87 v1(4204.87,3721.06)
GND: C1.2 C2.2 C4.2 C5.2 C6.2 C10.1 C11.1 C12.1 C13.1 C15.2 C16.1 C17.1 C18.2 C19.2 C21.1 CN1.1 D1.2 DC1.2 DC1.3 FPC1.2 FPC1.11 FPC1.12 FPC2.0 Q1.3 Q5.2 Q9.2 R1.2 R2.2 R3.1 R6.1 R8.2 R12.2 R14.1 R18.2 R25.2 U2.11 U3.3 U3.8 U4.2 U5.2 U7.8 U7.12 U9.6 U11.2 U12.7 U15.3 | length 3799.4
  Top Layer w10: C2.2 C1.2 ; Q5.2 3667.4,3698.03 3668.78,3699.41 3668.78,3824.63 3686.95,3842.8 3698.55,3842.8 U15.3 3735.84,3857.4 3752.14,3873.7 3792.74,3873.7 3809.04,3857.4 3815.16,3857.4 C21.1 3827.56,3882.44 v1(3825,3885) ; 3716.11,3580 FPC1.2 ; U7.8 3850,4764.99 v1(3832.99,4747.98) 3902.02,4747.98 v1(3935,4715) 3945,4705 v1(4000,4705) ; U7.12 v1(4000,4655) ; v1(4065,5765) 4119.57,5710.43 U3.3@4119.57,5705.75 ; v1(4180.18,5572.75) 4193.03,5585.61 4193.03,5605.55 4195,5607.52 v1(4195,5620) 4195,5629.49 4184.02,5640.48 4184.02,5667.84 U3.8
  Bottom Layer w10: U11.2 3380,4250.41 3339.49,4290.92 3339.49,4551.97 3437.99,4650.48 3437.99,4669.52 3380,4727.52 3380,4780 v1(3400,4800) ; v1(4000,4655) v1(4000,4705) ; v1(4070,4390) 4070,4196.66 CN1.1 4131.21,4135.45 4131.21,4037.68 4158.23,4010.65 v1(4182.68,4010.65)
  Bottom Layer w20: DC1.2 3813.47,6032.04 3790,6008.57 3790,5700 3670,5580 3670,5350 3720,5300 3720,5070 3835,4955 v1@3835,4755
  other v1: 3472.64,3451.09 3939.7,3547.62 3627.76,3548.86 3335,3595 4185,3850 3328.61,3866.12 4187.67,3893.54 3880.92,3929.04 3925,3930 3682.6,3979.37 3536.02,3997.99 3592.44,4025 3748.73,4044.75 3900,4230 3727.99,4269.13 3900.85,4269.69 4153.95,4496.27 3395.09,4529.96 3359.99,4900.61 3389.71,4900.61 3330,4902.71 3397.81,4958.97 3766.46,5015 3810,5015 3901.65,5085.79 3650,5120 3659.79,5174.75 3486.08,5178.01 3528.75,5178.01 3486.08,5213.01 3528.4,5213.01 3486.15,5247.65 3528.4,5247.65 3531.08,5278.01 3335.62,5643.64 3853.33,5646.01 3887.51,5646.01 3853.33,5680 3887.51,5680 3855,5710 3887.51,5710 3468.89,5764.44 4115,5795 4015,5870 3335,5900 3892.08,5909.09 4215,5910 3468.89,6064.44 4170,6105 3515,6130 3667.59,6130 4035,6187.11 3950.29,6188.12 4120,6190 4043.37,6211.38
GPIO15: FPC2.3 U10.3 | length 162.4
  Top Layer w10: FPC2.3@3482.61,4693.34 3576.66,4693.34 U10.3
GPIO16: FPC2.4 U10.4 | length 217.4
  Top Layer w10: FPC2.4@3482.61,4673.66 3533.48,4673.66 3595,4612.14 3595,4585 3625,4555 U10.4
GPIO17: FPC2.5 U10.5 | length 287.5
  Top Layer w10: FPC2.5@3482.61,4653.97 3485.4,4651.18 3518.82,4651.18 3580.55,4589.45 3580.55,4526.59 3625,4482.14 U10.5
INT: U11.8
PTC: FPC1.4 R7.1 | length 1854.4
  Top Layer w10: FPC1.4 3755.47,3745.51 v1(3777.48,3767.52) ; R7.1 3825,5055 v1(3855,5025)
  Bottom Layer w10: v1(3777.48,3767.52) 3803.24,3793.27 3963.27,3793.27 4008.75,3838.75 4008.75,4489.09 3975.76,4522.08 3975.76,4573.66 4078.94,4676.83 4078.94,4821.06 4065,4835 4000.64,4835 3930.98,4904.65 3930.98,4999.02 3920,5010 3870,5010 v1(3855,5025)
SCK: U9.2
SCL: FPC2.7 U11.3 | length 651.9
  Top Layer w10: U11.3@3375,4125 3321.6,4178.4 3321.6,4570.43 3365.77,4614.6 FPC2.7
SDA: FPC2.1 U11.4 | length 843.4
  Top Layer w10: v1(3415,4660) 3415,4665.1 3446.03,4696.13 3446.03,4723.48 3452.46,4729.92 3479.81,4729.92 FPC2.1@3482.61,4732.71
  Bottom Layer w10: U11.4@3400,4025 3365,4025 3321.6,4068.4 3321.6,4566.6 v1(3415,4660)
SPK1: SPK2.1 U7.14 | length 803.7
  Top Layer w10: v1(4080,4535) 4100,4555 U7.14
  Bottom Layer w10: v1(4080,4535) 4135,4590 4135,4904.64 4021.34,5018.31 4021.34,5075 4047.56,5101.23 SPK2.1
SPK2: SPK2.2 U7.13 | length 953.8
  Top Layer w10: v1(4028.02,4548.76) 4050,4570.74 U7.13
  Bottom Layer w10: v1(4028.02,4548.76) 4120.98,4641.72 4120.98,4898.84 4004.02,5015.81 4004.02,5204.02 4068.78,5268.78 SPK2.2
SW: FPC1.10 R3.2 U3.10 U9.4 U9.8 | length 2883.3
  Top Layer w10: FPC1.10 3888.88,3617.88 3981.45,3617.88 3989.66,3609.66 3989.66,3500.63 4008.38,3481.91 4121.25,3481.91 4232.86,3593.52 4232.86,3727.14 4215.94,3744.06 4172.54,3744.06 4162.87,3753.72 4162.87,3783.75 U9.4 4159.69,3903.36 4143.19,3919.86 4143.19,3949.88 U9.8 4143.19,3956.26 4143.19,4023.5 4154.2,4034.51 v1(4154.2,4047.2) ; R3.2 4205,5720.32 4190.43,5705.75 4224.25,5705.75 4232.86,5697.14 4232.86,5612.86 v1(4216.03,5596.03)
  Bottom Layer w10: v1(4154.2,4047.2) 4162.2,4047.2 4232.86,4117.86 4232.86,5579.19 v1(4216.03,5596.03)
USBDM: U3.6 U7.4 | length 956.4
  Top Layer w10: U7.4 4050.79,4809.81 v1(4050.79,4915) ; v1(4130,5620) 4147.13,5637.13 U3.6
  Bottom Layer w10: v1(4050.79,4915) 4050.79,4926.75 3975,5002.54 3975,5215 4050,5290 4050,5540 v1(4130,5620)
USBDP: U3.7 U7.5 | length 1015.5
  Top Layer w10: U7.5 4000,4869.26 v1(4019.27,4888.53) ; U3.7 4162.87,5612.13 v1(4165,5610)
  Bottom Layer w10: v1(4019.27,4888.53) 4056.83,4888.53 4073.78,4905.48 4073.78,4926.22 3990,5010 3990,5210 4064.02,5284.19 4064.02,5511.48 4162.54,5610 v1(4165,5610)
VIN: C1.1 C2.1 DC1.1 PTC1.1 R4.2 R13.1 R16.1 R17.1 R26.1 U4.4 U4.5 U12.1 U12.4 U12.5 U12.16 | length 4345.5
  Top Layer w10: R16.1 R17.1 3539.66,3822.88 3565.06,3848.28 3565.06,4026.86 3492.01,4099.91 3492.01,4140.77 3520,4168.76 R26.1 3530.98,4179.66 U12.16 ; U12.1 3616.27,4171.83 3616.27,4157.53 3627.02,4146.78 3627.02,4140.48 3640.49,4127.01 3659.53,4127.01 3673,4140.48 3673,4152.37 3678.16,4157.53 3678.16,4171.84 U12.4 ; U12.5@3725.19,4218.87 3727.58,4216.48 v1(3727.58,4213.87)
  Top Layer w20: U12.16 U12.1 ; v1(3625,5585) 3625,5615 3640,5630 ; U12.4 3720.19,4213.87 v1(3727.58,4213.87) ; 3935,5575 3990,5630 R4.2 ; PTC1.1 4150,5510 4222.86,5437.14 4222.86,4978.2 R13.1
  Top Layer w80: DC1.1 3612.51,5677.48 3740,5550 4105,5550 PTC1.1
  Bottom Layer w15: v1(3625,5585) 3640,5570 3640,5358.11 3648.48,5349.62 3648.48,5341.09 3698.48,5291.09 3698.48,5061.09 3700.98,5058.59 3700.98,4852.47 3704.51,4848.95 3704.51,4844.44 3719.44,4829.51 3723.95,4829.51 3807.5,4745.96 3807.5,4737.42 3822.43,4722.49 3838.9,4722.49 3858.17,4703.22 3858.17,4631.53 3834.64,4607.99 3775.55,4607.99 3770.55,4602.99 3762.62,4602.99 3749.15,4589.52 3749.15,4588.06 3746.65,4585.56 3746.65,4564.44 3761.58,4549.51 3770.12,4549.51 3957.07,4362.55 3957.07,4113.12 3950,4106.05 3768.8,4106.05 3727.58,4147.28 v1(3727.58,4213.87)
XCL: U11.6
XDA: U11.5
pads on no net: FPC2.2 FPC2.6 FPC2.8 U1.1 U1.2 U1.3 U1.4 U1.A1B12 U1.A4B9 U1.A8 U1.B1A12 U1.B4A9 U1.B8 U2.2 U2.3 U2.6 U2.7 U2.10 U5.4 U7.1 U7.2 U7.3 U7.6 U7.7 U10.1 U10.2 U12.6 U12.11 U12.17 U13.1 U13.4 U13.5 U15.1 U15.4 U15.5

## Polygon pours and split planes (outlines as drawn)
GND on Top Layer (solid, remove dead copper, pour order 0): 3000,6190 4390,6190 4390,3000 3000,3000
$2N173 on Bottom Layer (solid, remove dead copper, pour order 4): 3730,5645 4015,5645 cw(c4015,5635) 4025,5635 4025,5184.48 cw(c4015,5184.48) 4015,5174.48 3730,5174.48 cw(c3730,5184.48) 3720,5184.48 3720,5635 cw(c3730,5635)
GND on Bottom Layer (solid, remove dead copper, pour order 6): 3060,6300 4450,6300 4450,3110 3060,3110
VIN on Bottom Layer (solid, remove dead copper, pour order 2): 3914.92,5986.88 4166.89,5986.88 4166.89,5935.48 4160.98,5929.58 3915,5929.58 3914.92,5929.66

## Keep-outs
Top Layer:
  region: 3335,5540 3460,5540 3460,5360 3335,5360
  region: 3310,5635 3310,4980 3615.78,4980 3615.78,5374.22 3615,5375 3665,5375 3665,5635
Bottom Layer:
  region: 3670,6045 3855,6045 3855,6010 3810.88,6010 3810.88,5694.86 3690,5570.96 3690,5361.96 3735,5326.23 3735,4911.65 3873.11,4758.11 3875,4725 3810,4725 3810,4748.56 3700,4855.47 3700,5292.17 3649.6,5344.31 3649.6,5589.53 3765,5700 3765,6015 3670,6015
Board Outline Layer:
  circle w1: c3354,6093.89 r35.43
  circle w10: c3354,6093.89 r35.43
  circle w1: c3354,3495.47 r35.43
  circle w10: c3354,3495.47 r35.43
  circle w1: c4200.46,3495.47 r35.43
  circle w10: c4200.46,3495.47 r35.43
  lines w7.87: 3304.79,3436.58 3304.79,6152.79 cw(c3314.79,6152.79) 3314.79,6162.79 3786.91,6162.79 ccw(c3786.91,6172.79) 3796.91,6172.79 3796.91,6231.53 cw(c3806.91,6231.53) 3806.91,6241.53 4239.67,6241.53 cw(c4239.67,6231.53) 4249.67,6231.53 4249.67,3436.58 cw(c4239.67,3436.58) 4239.67,3426.58 3314.79,3426.58 cw(c3314.79,3436.58) 3304.79,3436.58

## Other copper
Top Layer:
  region net $2N1457: 3336.08,5463.01 3336.08,5538.01 3511.08,5538.01 3511.08,5463.01
  region net $2N1461: 3561.08,5422.61 3586.08,5423.01 3586.08,5368.01 3662.09,5368.01 3662.09,5324.79 3561.08,5324.79
  region net GND: 3546.08,5423.01 3521.84,5423.01 3521.84,5353.01 3466.08,5353.01 3466.08,5155.78 3546.08,5155.78
  region net VIN: 3521.17,5470.98 3521.17,5662.73 3520.78,5662.73 3520.78,5890 3625,5890 3725,5990 3725,6130 4120.98,6130 4120.98,6037.87 4073.77,6085 4005,6085 3955,6040 3947.56,6040.22 3946.42,6081.6 3846.6,6081.6 3825,6060 3825,5925 3727.98,5827.98 3727.98,5757.98 3632.73,5662.73 3604.82,5662.73 3604.82,5512.44 3586.04,5512.44 3585.67,5471.22 3562.75,5471.22 3562.99,5514.9 3548.36,5515 3548.36,5470.98
  region net 5V: 3335.85,5043.09 3336.08,5043.09 3336.08,5433.01 3451.08,5433.01 3451.08,5118.01 3559.71,5118.01 3559.71,5313.01 3613.49,5313.01 3613.49,5033.01 3496.91,5033.01 3496.91,4916.48 3415,4916.48 3415,4940 3469.89,4940 3469.89,4991.42 3390.25,4991.42 3390.25,4985.85 3335.85,4985.85
  region net GND: 3459.05,4975.38 3336.57,4975.31 3336.57,4884.64 3405.75,4884.64 3405,4955 3459.05,4955
  region net 3V3: 3505,5016.2 3505,4950 3560.97,4950 3560.97,4980.97 3620.45,4980.97 3620.45,5016.2
  region net 3V3: 3835,3590 3835,3540 3845,3530 3859.68,3530 3869.68,3540 3869.68,3590 3859.68,3600 3845,3600
  region net VIN: 3652.51,5677.48 3572.51,5677.48 3572.78,5684.14 3573.49,5690.75 3574.53,5697.25 3575.77,5703.59 3578.35,5715.61 3579.45,5721.17 3580.26,5726.37 3580.65,5731.15 3580.65,5733.37 3580.5,5735.47 3580.18,5737.43 3579.68,5739.26 3578.99,5740.94 3578.08,5742.48 3576.95,5743.86 3575.57,5745.07 3573.93,5746.12 3572.02,5746.99 3569.82,5747.68 3567.32,5748.18 3564.49,5748.49 3561.33,5748.59 3663.7,5748.59 3660.54,5748.49 3657.71,5748.18 3655.21,5747.68 3653.01,5746.99 3651.1,5746.12 3649.46,5745.07 3648.08,5743.86 3646.95,5742.48 3646.04,5740.94 3645.35,5739.26 3644.85,5737.43 3644.53,5735.47 3644.38,5733.37 3644.38,5731.15 3644.77,5726.37 3645.58,5721.17 3646.68,5715.61 3649.26,5703.59 3650.5,5697.25 3651.54,5690.75 3652.25,5684.14
  region net $2N1457: 3509.36,5464.02 3499.36,5464.02 ccw(c3490.5,5464.02) 3491.86,5472.77 3509.22,5472.77 ccw(c3781.11,5472.77)
  region net $2N1458: 3493.74,5427.82 3503.74,5427.82 ccw(c3509.22,5430.66) 3509.22,5424.49 3488.27,5424.49 ccw(c3488.27,5430.66)
  region net CC1: 4075,5845 4075,5855 4076.06,5855.09 4077.03,5855.34 4078.78,5856.23 4080.39,5857.5 4081.99,5858.95 4081.99,5841.05 4080.39,5842.5 4078.78,5843.77 4077.03,5844.66 4076.06,5844.91
  region net 5V: 3946.91,4643.7 3936.3,4633.09 3934.68,4634.85 3933.19,4636.38 3932.39,4637 3931.51,4637.5 3930.51,4637.84 3929.33,4638.01 3941.99,4650.67 3942.16,4649.49 3942.5,4648.49 3943,4647.61 3943.62,4646.81 3945.15,4645.32
  region net USBDM: 4138.07,5635.14 4145.14,5628.07 4144.41,5627.21 4143.79,5626.24 4142.84,5624.02 4142.26,5621.65 4141.99,5619.33 4129.33,5631.99 4131.65,5632.26 4134.02,5632.84 4136.24,5633.79 4137.21,5634.41
  region net DN1: 4058.07,5685.14 4065.14,5678.07 4064.41,5677.21 4063.79,5676.24 4062.84,5674.02 4062.26,5671.65 4061.99,5669.33 4049.33,5681.99 4051.65,5682.26 4054.02,5682.84 4056.24,5683.79 4057.21,5684.41
  region net DP1: 4068.07,5645.14 4075.14,5638.07 4074.41,5637.21 4073.79,5636.24 4072.84,5634.02 4072.26,5631.65 4071.99,5629.33 4059.33,5641.99 4061.65,5642.26 4064.02,5642.84 4066.24,5643.79 4067.21,5644.41
  region net PTC: 3839.86,5033.07 3846.93,5040.14 3847.79,5039.41 3848.76,5038.79 3850.98,5037.84 3853.35,5037.26 3855.67,5036.99 3843.01,5024.33 3842.74,5026.65 3842.16,5029.02 3841.21,5031.24 3840.59,5032.21
  region net 3V3: 3705,5368.59 3695,5368.59 3694.91,5369.71 3694.66,5370.84 3693.77,5373.07 3692.5,5375.17 3691.05,5376.99 3708.95,5376.99 3707.5,5375.17 3706.23,5373.07 3705.34,5370.84 3705.09,5369.71
  region net 3V3: 3848.89,3590.76 3858.89,3590.76 3858.98,3589.64 3859.23,3588.51 3860.13,3586.28 3861.39,3584.19 3862.85,3582.36 3844.94,3582.36 3846.4,3584.19 3847.66,3586.28 3848.56,3588.51 3848.81,3589.64
  region net GND: 4200,5607.52 4190,5607.52 4189.91,5608.47 4189.66,5609.16 4189.27,5609.65 4188.77,5610.04 4187.5,5610.78 4186.79,5611.29 4186.05,5611.99 4203.95,5611.99 4203.21,5611.29 4202.5,5610.78 4201.23,5610.04 4200.73,5609.65 4200.34,5609.16 4200.09,5608.47
  region net GND: 4181.94,5635.48 4192.59,5638.97 4197.26,5634.02 4199.38,5631.95 4202.32,5629.52 4185.01,5626.66 4185.59,5627.84 4185.8,5629 4185.67,5630.13 4185.27,5631.25 4184.65,5632.34 4183.85,5633.41
  region net 3V3: 3858.89,3592.59 3848.89,3592.59 ccw(c3724.2,3592.59) 3847.99,3607.59 3859.8,3607.59 ccw(c3983.59,3592.59)
  region net GND: 3721.11,3592.59 3711.11,3592.59 ccw(c3586.41,3592.59) 3710.2,3607.59 3722.01,3607.59 ccw(c3845.8,3592.59)
  region net ADC_VIN: 3691.41,3673.59 3701.41,3673.59 ccw(c3823.07,3673.59) 3702.32,3658.77 3690.51,3658.77 ccw(c3569.76,3673.59)
  region net 5V: 3928.24,4641.16 3950.14,4640.46 3952.22,4638.3 3954.24,4635.99 3956.12,4633.55 3957.81,4631 3959.24,4628.33 3960.34,4625.57 3961.05,4622.72 3961.3,4619.8 3938.7,4619.8 3938.47,4622.63 3937.8,4625.52 3936.77,4628.43 3935.43,4631.29 3933.85,4634.05 3932.08,4636.65 3930.19,4639.04
Bottom Layer:
  region net 3V3: 3505,5016.2 3505,4950 3561.8,4950 3561.8,4980.97 3590.71,4980.97 3590.71,5016.2
  region net GND: 3830,5730 3830,5630 3904.01,5630 3905.02,5631.01 3905.02,5730
  region net GND: 3724.12,6042.04 3724.12,6022.04 3722.25,6021.95 3720.3,6021.7 3716.2,6020.75 3711.99,6019.27 3707.79,6017.35 3703.76,6015.08 3700.04,6012.55 3696.78,6009.84 3694.12,6007.04 3694.12,6057.04 3696.78,6054.24 3700.04,6051.53 3703.76,6049 3707.79,6046.73 3711.99,6044.81 3716.2,6043.33 3720.3,6042.38 3722.25,6042.13
  region net DP: 4031.46,6046.46 4038.54,6053.54 4039.32,6052.87 4040.12,6052.43 4040.93,6052.17 4041.78,6052.04 4045.67,6051.99 4033.01,6039.33 4032.96,6043.22 4032.83,6044.07 4032.57,6044.88 4032.13,6045.68
  region net DP: 4015.43,6055 4015.43,6045 4014.31,6044.91 4013.17,6044.66 4010.94,6043.77 4008.85,6042.5 4007.02,6041.05 4007.02,6058.95 4008.85,6057.5 4010.94,6056.23 4013.17,6055.34 4014.31,6055.09
  region net CC1: 4140.18,5893.11 4131.55,5898.62 4132.27,5899.48 4132.89,5900.49 4133.82,5902.82 4134.32,5905.31 4134.4,5907.66 4148.52,5896.65 4146.28,5896.17 4144.04,5895.47 4141.96,5894.47
  region net CC1: 4098.07,5865.14 4105.14,5858.07 4104.41,5857.21 4103.79,5856.24 4102.84,5854.02 4102.26,5851.65 4101.99,5849.33 4089.33,5861.99 4091.65,5862.26 4094.02,5862.84 4096.24,5863.79 4097.21,5864.41
  region net 5V: 3913.59,4642.5 3913.59,4657.5 3915.98,4657.41 3918.12,4657.38 3919.12,4657.5 3920.09,4657.77 3921.05,4658.24 3921.99,4658.95 3921.99,4641.05 3921.05,4641.76 3920.09,4642.23 3919.12,4642.5 3918.12,4642.62 3915.98,4642.59
  region net ESP_RX: 3828.07,3725.14 3835.14,3718.07 3834.41,3717.21 3833.79,3716.24 3832.84,3714.02 3832.26,3711.65 3831.99,3709.33 3819.33,3721.99 3821.65,3722.26 3824.02,3722.84 3826.24,3723.79 3827.21,3724.41
  region net DP1: 4047.82,5615.75 4044.47,5626.55 4045.85,5628.21 4046.99,5630.11 4047.94,5632.14 4048.74,5634.17 4057.11,5618.35 4056.02,5618.51 4054.8,5618.5 4052.19,5618.03 4049.72,5617.08 4048.67,5616.45
  region net 3V3: 3708.07,5400.14 3715.14,5393.07 3714.41,5392.21 3713.79,5391.24 3712.84,5389.02 3712.26,5386.65 3711.99,5384.33 3699.33,5396.99 3701.65,5397.26 3704.02,5397.84 3706.24,5398.79 3707.21,5399.41
  region net 3V3: 4185.52,5652.41 4190.11,5661.96 4192.29,5659.86 4193.37,5658.97 4194.46,5658.28 4195.56,5657.86 4196.66,5657.77 4197.78,5658.08 4198.91,5658.87 4199.07,5640.99 4195.64,5643.86 4192.2,5646.6 4188.8,5649.39

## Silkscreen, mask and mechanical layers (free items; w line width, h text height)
Top Solder Mask Layer:
  region: 3925,5175.41 3723.52,5175 3723.52,5426.99 3781.53,5485 3995,5485 3995,5310 3925,5240
Bottom Solder Mask Layer:
  region: 3735,5430 3785,5480 3945,5480 3945,5255 3930,5240 3930,5230 3735,5230
Mechanical Layer:
  circle w1: c3354,6093.89 r35.43
  circle w1: c3354,3495.47 r35.43
  circle w1: c4200.46,3495.47 r35.43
